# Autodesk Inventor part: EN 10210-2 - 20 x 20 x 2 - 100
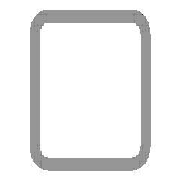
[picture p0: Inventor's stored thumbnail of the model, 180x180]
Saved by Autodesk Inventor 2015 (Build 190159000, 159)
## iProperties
Created: 2015-05
Part Number: EN 10210-2 - 20 x 20 x 2 - 100
Material: Steel, Mild
Description: Tube
Document SubType Name: Modeling
Standard: DIN
Designer: TREINA6
Standard Revision: 1997
Standards Organization: DIN
Language: en-US
Size Designation: 20 x 20 x 2
Categories: <MemberInstance><Categories><Category DisplayName="Structural Shapes" InternalName="089c4875-fa83-4c05-b084-43b9cc11f5ed" Mnemonic="GRDR"><CategoryParameter Dis
Stock Number: 20 x 20 x 2
Density: 7.85 g/cm^3
Appearance: Semi-Polished
_CCFamilyMember: 1
_CCFamilyDisplayName: DIN EN 10210-2 (Square) - Tube
_FrameMemberDoc: Frame Member File
_Version: 15.0.0
_GetPNFromCC: 1
IsCustomPart: 1
Author: TREINA6
G_L: 100,000 mm
G_W: 20,000 mm
G_H: 20,000 mm
+63C693C6-E9A6-4038-8A18-7BD96AE36099+CUTDETAIL1: Miter 45,00 deg
+2BFCD211-69C8-43B1-8338-467FB59833FA+CUTDETAIL2: Miter 45,00 deg
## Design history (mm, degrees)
node "Start plane"
node "End plane"
sketch "Sketch"
  geometry: L1 (-10, -7)-(-10, 7); L2 (-7, 10)-(7, 10); L3 (10, 7)-(10, -7); L4 (7, -10)-(-7, -10); L5 (-7, 8)-(7, 8); L6 (8, 7)-(8, -7); L7 (7, -8)-(-7, -8); L8 (-8, -7)-(-8, 7); L9 (0, 14.87)-(0, -14.87) reference; L10 (-14.87, 0)-(14.87, 0) reference; A1 r 3 centre (-7, -7) between (-10, -7) and (-7, -10); A2 r 3 centre (-7, 7) between (-7, 10) and (-10, 7); A3 r 3 centre (7, 7) between (10, 7) and (7, 10); A4 r 3 centre (7, -7) between (7, -10) and (10, -7); A5 r 1 centre (-7, 7) between (-7, 8) and (-8, 7); A6 r 1 centre (7, 7) between (8, 7) and (7, 8); A7 r 1 centre (7, -7) between (7, -8) and (8, -7); A8 r 1 centre (-7, -7) between (-8, -7) and (-7, -8)
  constraints: 16 end point, 16 point on circle, 8 centre point, 8 tangent, 4 parallel, 3 equal radius, 2 perpendicular, 7 other
  dimensions: "d7" = 3 radius of A1 (= G_IR); "d10" = 20 distance between parallel lines of L2 L4 (= G_H); "d11" = 20 distance between parallel lines of L1 L3 (= G_W); "d12" = 2 distance between parallel lines of L3 L6 (= G_T); "d15" = 10 distance between parallel lines of L2 L10 (= 0.5 x d10); "d16" = 10 distance between parallel lines of L9 L3 (= 0.5 x d11)
extrude "Body" new body sketch "Sketch" stored distance "d3" = 100 (= G_L); taper "d4" = 0 deg
node "Driven Length"
  sketch "Sketch3"
    geometry: L1 (0, 0)-(10, 0) reference
    constraints: 2 end point, 1 horizontal
  workplane "Work Plane3"
  sketch "Sketch4"
    geometry: L1 (-2, 0)-(12, 0) reference; L2 (-2, 100)-(12, 100) reference
    dimensions: "d18" = 100 distance between parallel lines of L1 L2 (derived)
workplane "Work Plane4"
split "Split1"
workplane "Work Plane5"
split "Split2"
body "Solid1"
other parameters: "G_W" = 20 [user parameter; used in 1 equation term], "G_H" = 20 [user parameter; used in 1 equation term], "G_T" = 2 [user parameter; used in 1 equation term], "G_IR" = 3 [user parameter; used in 1 equation term], "G_L" = 100 (= d18) [user parameter; used in 1 equation term], "G_OFFSET_START" = 0 [user parameter; used in 1 equation term], "G_OFFSET_END" = 0 [user parameter; used in 1 equation term], "d13" = 0 (computed from G_OFFSET_START), "d17" = 90 deg
